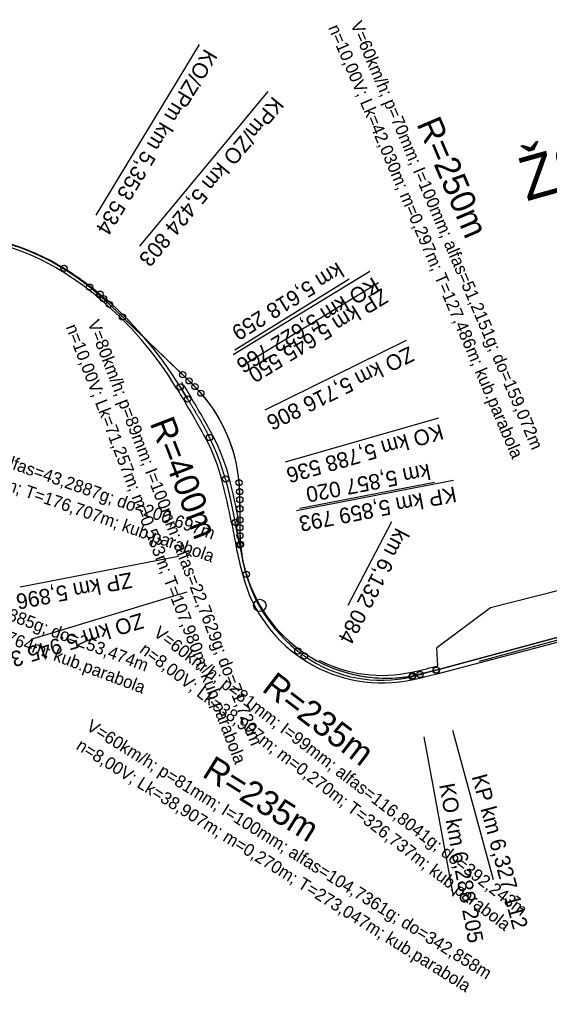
# Model space of a CAD drawing. Extents: x -504999 to -493096, y -1330712 to -1305226.
# Drawn here: x -502934 to -502082, y -1330075 to -1328510 of the extents above; entities that cross this region are included whole.
import ezdxf

# ---------------------------------------------------------------- set-up
doc = ezdxf.new("R2010")
doc.units = 0
for name, color, linetype in [('0_HM', 7, 'Continuous'), ('0_NAVRH V_60_povodnej osi', 7, 'Continuous'), ('0_NAVRH V_80KMH', 7, 'Continuous'), ('0_obluky', 7, 'Continuous'), ('0_STANICE', 7, 'Continuous'), ('0_stanicenie oblukov', 7, 'Continuous'), ('0_SUčASNA KOLAJ', 7, 'Continuous'), ('Level 1', 7, 'Continuous'), ('PHS', 7, 'Continuous')]:
    doc.layers.add(name, color=color, linetype=linetype)

msp = doc.modelspace()

# ---------------------------------------------------------------- linework, layer by layer
at = {"layer": '0_HM'}
msp.add_circle((-502547.5, -1329452.5), 10, dxfattribs=at)
at = {"layer": '0_NAVRH V_60_povodnej osi'}
for p, q in [((-502769, -1328987.9), (-502671.7, -1329081.4)), ((-502579.7, -1329297.2), (-502579.7, -1329317.3))]:
    msp.add_line(p, q, dxfattribs=at)
for points in [[(-502768.3, -1328988.6), (-502769, -1328987.9), (-502769.7, -1328987.2), (-502770.4, -1328986.6), (-502771.1, -1328985.9), (-502771.9, -1328985.2), (-502772.6, -1328984.5), (-502773.3, -1328983.8), (-502774, -1328983.1), (-502774.8, -1328982.4), (-502775.5, -1328981.7), (-502776.2, -1328981), (-502776.9, -1328980.3), (-502777.7, -1328979.6), (-502778.4, -1328978.9), (-502779.1, -1328978.2), (-502779.8, -1328977.5), (-502780.6, -1328976.8), (-502781.3, -1328976.2), (-502782, -1328975.5), (-502782.7, -1328974.8), (-502783.5, -1328974.1), (-502784.2, -1328973.4), (-502784.9, -1328972.7), (-502785.7, -1328972), (-502786.4, -1328971.3), (-502787.1, -1328970.6), (-502787.9, -1328970), (-502788.6, -1328969.3), (-502789.3, -1328968.6), (-502790.1, -1328967.9), (-502790.8, -1328967.2), (-502791.5, -1328966.5), (-502792.3, -1328965.9), (-502793, -1328965.2), (-502793.7, -1328964.5), (-502794.5, -1328963.8), (-502795.2, -1328963.1), (-502796, -1328962.5), (-502796.7, -1328961.8), (-502797.4, -1328961.1), (-502798.2, -1328960.4), (-502798.9, -1328959.8), (-502799.7, -1328959.1), (-502800.4, -1328958.4), (-502801.2, -1328957.8), (-502801.9, -1328957.1), (-502802.7, -1328956.4), (-502803.4, -1328955.8), (-502804.2, -1328955.1), (-502804.9, -1328954.4), (-502805.7, -1328953.8), (-502806.4, -1328953.1), (-502807.2, -1328952.4), (-502807.9, -1328951.8), (-502808.7, -1328951.1), (-502809.5, -1328950.5), (-502810.2, -1328949.8), (-502811, -1328949.2), (-502811.8, -1328948.5), (-502812.5, -1328947.9), (-502813.3, -1328947.2), (-502814.1, -1328946.6), (-502814.8, -1328945.9), (-502815.6, -1328945.3), (-502816.4, -1328944.6), (-502817.2, -1328944), (-502817.9, -1328943.4), (-502818.7, -1328942.7), (-502819.5, -1328942.1), (-502820.3, -1328941.5), (-502821.1, -1328940.8)], [(-502671.7, -1329081.4), (-502671, -1329082.1), (-502670.3, -1329082.8), (-502669.6, -1329083.5), (-502668.9, -1329084.2), (-502668.1, -1329084.9), (-502667.4, -1329085.6), (-502666.7, -1329086.2), (-502666, -1329086.9), (-502665.3, -1329087.6), (-502664.5, -1329088.3), (-502663.8, -1329089), (-502663.1, -1329089.7), (-502662.4, -1329090.4), (-502661.7, -1329091.1), (-502661, -1329091.8), (-502660.2, -1329092.5), (-502659.5, -1329093.2), (-502658.8, -1329093.9), (-502658.1, -1329094.6), (-502657.4, -1329095.3), (-502656.7, -1329096.1), (-502656, -1329096.8), (-502655.3, -1329097.5), (-502654.6, -1329098.2), (-502653.9, -1329098.9), (-502653.2, -1329099.6), (-502652.5, -1329100.3), (-502651.8, -1329101), (-502651.1, -1329101.8), (-502650.4, -1329102.5), (-502649.7, -1329103.2), (-502649, -1329103.9), (-502648.3, -1329104.7), (-502647.7, -1329105.4), (-502647, -1329106.1), (-502646.3, -1329106.9), (-502645.6, -1329107.6), (-502644.9, -1329108.4), (-502644.3, -1329109.1), (-502643.6, -1329109.8), (-502642.9, -1329110.6), (-502642.3, -1329111.3)], [(-502579.7, -1329297.2), (-502579.7, -1329296.2), (-502579.7, -1329295.2), (-502579.7, -1329294.2), (-502579.7, -1329293.2), (-502579.7, -1329292.2), (-502579.7, -1329291.2), (-502579.7, -1329290.2), (-502579.7, -1329289.2), (-502579.7, -1329288.2), (-502579.7, -1329287.2), (-502579.8, -1329286.2), (-502579.8, -1329285.2), (-502579.8, -1329284.2), (-502579.8, -1329283.2), (-502579.8, -1329282.2), (-502579.8, -1329281.2), (-502579.8, -1329280.2), (-502579.8, -1329279.2), (-502579.8, -1329278.2), (-502579.9, -1329277.2), (-502579.9, -1329276.2), (-502579.9, -1329275.2), (-502579.9, -1329274.2), (-502580, -1329273.2), (-502580, -1329272.2), (-502580, -1329271.2), (-502580.1, -1329270.2), (-502580.1, -1329269.2), (-502580.1, -1329268.2), (-502580.2, -1329267.2), (-502580.2, -1329266.2), (-502580.3, -1329265.2), (-502580.3, -1329264.2), (-502580.4, -1329263.2), (-502580.4, -1329262.2), (-502580.5, -1329261.2), (-502580.6, -1329260.2), (-502580.6, -1329259.2), (-502580.7, -1329258.2), (-502580.8, -1329257.2), (-502580.9, -1329256.2), (-502580.9, -1329255.2)], [(-502579.7, -1329315.2), (-502579.7, -1329316.2), (-502579.7, -1329317.3), (-502579.7, -1329318.3), (-502579.7, -1329319.3), (-502579.7, -1329320.3), (-502579.7, -1329321.3), (-502579.7, -1329322.4), (-502579.7, -1329323.4), (-502579.7, -1329324.4), (-502579.7, -1329325.4), (-502579.7, -1329326.5), (-502579.7, -1329327.5), (-502579.7, -1329328.5), (-502579.6, -1329329.5), (-502579.6, -1329330.6), (-502579.6, -1329331.6), (-502579.6, -1329332.6), (-502579.6, -1329333.6), (-502579.6, -1329334.6), (-502579.5, -1329335.7), (-502579.5, -1329336.7), (-502579.5, -1329337.7), (-502579.5, -1329338.7), (-502579.4, -1329339.8), (-502579.4, -1329340.8), (-502579.3, -1329341.8), (-502579.3, -1329342.8), (-502579.3, -1329343.9), (-502579.2, -1329344.9), (-502579.2, -1329345.9), (-502579.1, -1329346.9), (-502579, -1329347.9), (-502579, -1329349), (-502578.9, -1329350), (-502578.8, -1329351), (-502578.8, -1329352), (-502578.7, -1329353.1), (-502578.6, -1329354.1)]]:
    msp.add_lwpolyline(points, dxfattribs=at)
for centre in [(-502821.1, -1328940.8), (-502768.3, -1328988.6), (-502671.7, -1329081.4), (-502642.3, -1329111.3), (-502580.9, -1329255.2), (-502579.7, -1329297.2), (-502579.7, -1329315.2), (-502578.6, -1329354.1), (-502301.9, -1329565.6), (-502264.1, -1329556.5)]:
    msp.add_circle(centre, 5, dxfattribs=at)
for centre, radius, start, end in [((-503071.5, -1329252.8), 400, 51.2431, 87.5506), ((-502830, -1329276.4), 250, 4.8619, 41.3185), ((-502344.4, -1329334.5), 235, 184.7885, 280.422)]:
    msp.add_arc(centre, radius, start, end, dxfattribs=at)
at = {"layer": '0_NAVRH V_80KMH'}
msp.add_lwpolyline([(-502264.1, -1329556.5), (-502265.1, -1329556.7), (-502266.1, -1329557), (-502267.1, -1329557.3), (-502268.1, -1329557.5), (-502269, -1329557.8), (-502270, -1329558.1), (-502271, -1329558.3), (-502272, -1329558.6), (-502273, -1329558.9), (-502274, -1329559.1), (-502275, -1329559.4), (-502276, -1329559.6), (-502277, -1329559.9), (-502277.9, -1329560.2), (-502278.9, -1329560.4), (-502279.9, -1329560.7), (-502280.9, -1329560.9), (-502281.9, -1329561.2), (-502282.9, -1329561.4), (-502283.9, -1329561.7), (-502284.9, -1329561.9), (-502285.9, -1329562.1), (-502286.9, -1329562.4), (-502287.9, -1329562.6), (-502288.9, -1329562.9), (-502289.9, -1329563.1), (-502290.9, -1329563.3), (-502291.9, -1329563.5), (-502292.9, -1329563.8), (-502293.9, -1329564), (-502294.9, -1329564.2), (-502295.9, -1329564.4), (-502296.9, -1329564.6), (-502297.9, -1329564.8), (-502298.9, -1329565), (-502299.9, -1329565.2), (-502300.9, -1329565.4), (-502301.9, -1329565.6)], dxfattribs=at)
at = {"layer": '0_obluky'}
for p, q in [((-502663.7, -1329120.6), (-502675.6, -1329101.2)), ((-502675.6, -1329101.2), (-502663.7, -1329120.6)), ((-502580, -1329355.1), (-502587, -1329318.8)), ((-502587, -1329318.8), (-502580, -1329355.1)), ((-502264, -1329556.4), (-501516.9, -1329353.9))]:
    msp.add_line(p, q, dxfattribs=at)
for points in [[(-502804.4, -1328952.1), (-502805.2, -1328951.4), (-502806, -1328950.8), (-502806.8, -1328950.2), (-502807.5, -1328949.5), (-502808.3, -1328948.9), (-502809.1, -1328948.3), (-502809.9, -1328947.6), (-502810.7, -1328947), (-502811.4, -1328946.4), (-502812.2, -1328945.7), (-502813, -1328945.1), (-502813.8, -1328944.5), (-502814.6, -1328943.9), (-502815.4, -1328943.2), (-502816.2, -1328942.6), (-502816.9, -1328942), (-502817.7, -1328941.4), (-502818.5, -1328940.8), (-502819.3, -1328940.2), (-502820.1, -1328939.5), (-502820.9, -1328938.9), (-502821.7, -1328938.3), (-502822.5, -1328937.7), (-502823.3, -1328937.1), (-502824.1, -1328936.5), (-502824.9, -1328935.9), (-502825.7, -1328935.3), (-502826.5, -1328934.7), (-502827.3, -1328934.1), (-502828.1, -1328933.5), (-502828.9, -1328932.9), (-502829.7, -1328932.3), (-502830.5, -1328931.7), (-502831.3, -1328931.1), (-502832.2, -1328930.5), (-502833, -1328929.9), (-502833.8, -1328929.4), (-502834.6, -1328928.8), (-502835.4, -1328928.2), (-502836.2, -1328927.6), (-502837.1, -1328927), (-502837.9, -1328926.4), (-502838.7, -1328925.9), (-502839.5, -1328925.3), (-502840.3, -1328924.7), (-502841.2, -1328924.2), (-502842, -1328923.6), (-502842.8, -1328923), (-502843.6, -1328922.5), (-502844.5, -1328921.9), (-502845.3, -1328921.3), (-502846.1, -1328920.8), (-502847, -1328920.2), (-502847.8, -1328919.7), (-502848.7, -1328919.1), (-502849.5, -1328918.6), (-502850.3, -1328918), (-502851.2, -1328917.5), (-502852, -1328916.9), (-502852.9, -1328916.4), (-502853.7, -1328915.8), (-502854.6, -1328915.3), (-502855.4, -1328914.7), (-502856.3, -1328914.2), (-502857.1, -1328913.7), (-502858, -1328913.1), (-502858.8, -1328912.6), (-502859.7, -1328912.1), (-502860.5, -1328911.6), (-502861.4, -1328911), (-502862.2, -1328910.5)], [(-502663.7, -1329120.6), (-502663.2, -1329121.5), (-502662.7, -1329122.3), (-502662.1, -1329123.2), (-502661.6, -1329124), (-502661.1, -1329124.9), (-502660.6, -1329125.8), (-502660, -1329126.6), (-502659.5, -1329127.5), (-502659, -1329128.3), (-502658.5, -1329129.2), (-502658, -1329130), (-502657.4, -1329130.9), (-502656.9, -1329131.8), (-502656.4, -1329132.6), (-502655.9, -1329133.5), (-502655.4, -1329134.3), (-502654.8, -1329135.2), (-502654.3, -1329136), (-502653.8, -1329136.9), (-502653.3, -1329137.8), (-502652.8, -1329138.6), (-502652.3, -1329139.5), (-502651.7, -1329140.3), (-502651.2, -1329141.2), (-502650.7, -1329142.1), (-502650.2, -1329142.9), (-502649.7, -1329143.8), (-502649.2, -1329144.7), (-502648.7, -1329145.5), (-502648.2, -1329146.4), (-502647.7, -1329147.2), (-502647.2, -1329148.1), (-502646.6, -1329149), (-502646.1, -1329149.8), (-502645.6, -1329150.7), (-502645.1, -1329151.6), (-502644.6, -1329152.4), (-502644.1, -1329153.3), (-502643.6, -1329154.2), (-502643.1, -1329155.1), (-502642.6, -1329155.9), (-502642.1, -1329156.8), (-502641.6, -1329157.7), (-502641.1, -1329158.5), (-502640.7, -1329159.4), (-502640.2, -1329160.3), (-502639.7, -1329161.2), (-502639.2, -1329162.1), (-502638.7, -1329162.9), (-502638.2, -1329163.8), (-502637.7, -1329164.7), (-502637.2, -1329165.6), (-502636.8, -1329166.4), (-502636.3, -1329167.3), (-502635.8, -1329168.2), (-502635.3, -1329169.1), (-502634.9, -1329170), (-502634.4, -1329170.9), (-502633.9, -1329171.8), (-502633.5, -1329172.6), (-502633, -1329173.5), (-502632.5, -1329174.4), (-502632.1, -1329175.3), (-502631.6, -1329176.2), (-502631.1, -1329177.1), (-502630.7, -1329178), (-502630.2, -1329178.9), (-502629.8, -1329179.8), (-502629.3, -1329180.7), (-502628.9, -1329181.6), (-502628.4, -1329182.5)], [(-502587, -1329318.8), (-502587.2, -1329317.8), (-502587.4, -1329316.9), (-502587.6, -1329315.9), (-502587.8, -1329314.9), (-502588, -1329313.9), (-502588.2, -1329312.9), (-502588.4, -1329311.9), (-502588.5, -1329310.9), (-502588.7, -1329310), (-502588.9, -1329309), (-502589.1, -1329308), (-502589.3, -1329307), (-502589.5, -1329306), (-502589.7, -1329305), (-502589.9, -1329304.1), (-502590.1, -1329303.1), (-502590.3, -1329302.1), (-502590.5, -1329301.1), (-502590.7, -1329300.1), (-502590.9, -1329299.1), (-502591.1, -1329298.2), (-502591.3, -1329297.2), (-502591.5, -1329296.2), (-502591.7, -1329295.2), (-502591.9, -1329294.2), (-502592.1, -1329293.2), (-502592.3, -1329292.3), (-502592.5, -1329291.3), (-502592.7, -1329290.3), (-502592.9, -1329289.3), (-502593.1, -1329288.3), (-502593.3, -1329287.4), (-502593.5, -1329286.4), (-502593.7, -1329285.4), (-502593.9, -1329284.4), (-502594.1, -1329283.4), (-502594.3, -1329282.4), (-502594.6, -1329281.5), (-502594.8, -1329280.5), (-502595, -1329279.5), (-502595.2, -1329278.5), (-502595.4, -1329277.5), (-502595.6, -1329276.6), (-502595.9, -1329275.6), (-502596.1, -1329274.6), (-502596.3, -1329273.6), (-502596.5, -1329272.7), (-502596.8, -1329271.7), (-502597, -1329270.7), (-502597.2, -1329269.7), (-502597.5, -1329268.8), (-502597.7, -1329267.8), (-502597.9, -1329266.8), (-502598.2, -1329265.8), (-502598.4, -1329264.9), (-502598.7, -1329263.9), (-502598.9, -1329262.9), (-502599.2, -1329261.9), (-502599.4, -1329261), (-502599.7, -1329260), (-502599.9, -1329259), (-502600.2, -1329258), (-502600.4, -1329257.1), (-502600.7, -1329256.1), (-502601, -1329255.1), (-502601.2, -1329254.2), (-502601.5, -1329253.2), (-502601.8, -1329252.2), (-502602, -1329251.2), (-502602.3, -1329250.3), (-502602.6, -1329249.3)], [(-502580, -1329355.1), (-502579.8, -1329356.1), (-502579.7, -1329357.1), (-502579.5, -1329358.1), (-502579.3, -1329359.1), (-502579.1, -1329360.1), (-502578.9, -1329361.1), (-502578.7, -1329362.1), (-502578.5, -1329363.1), (-502578.3, -1329364.1), (-502578.1, -1329365.1), (-502577.9, -1329366), (-502577.7, -1329367), (-502577.5, -1329368), (-502577.3, -1329369), (-502577.1, -1329370), (-502576.9, -1329371), (-502576.7, -1329372), (-502576.5, -1329373), (-502576.3, -1329374), (-502576.1, -1329375), (-502575.9, -1329376), (-502575.7, -1329377), (-502575.5, -1329377.9), (-502575.2, -1329378.9), (-502575, -1329379.9), (-502574.8, -1329380.9), (-502574.6, -1329381.9), (-502574.3, -1329382.9), (-502574.1, -1329383.9), (-502573.9, -1329384.9), (-502573.7, -1329385.8), (-502573.4, -1329386.8), (-502573.2, -1329387.8), (-502572.9, -1329388.8), (-502572.7, -1329389.8), (-502572.4, -1329390.8), (-502572.2, -1329391.7), (-502571.9, -1329392.7), (-502571.7, -1329393.7), (-502571.4, -1329394.7), (-502571.2, -1329395.7), (-502570.9, -1329396.6), (-502570.6, -1329397.6), (-502570.3, -1329398.6), (-502570.1, -1329399.6), (-502569.8, -1329400.5), (-502569.5, -1329401.5), (-502569.2, -1329402.5)], [(-502264, -1329556.4), (-502264.9, -1329556.7), (-502265.9, -1329557), (-502266.9, -1329557.2), (-502267.9, -1329557.5), (-502268.9, -1329557.8), (-502269.9, -1329558), (-502270.9, -1329558.3), (-502271.9, -1329558.6), (-502272.8, -1329558.8), (-502273.8, -1329559.1), (-502274.8, -1329559.3), (-502275.8, -1329559.6), (-502276.8, -1329559.9), (-502277.8, -1329560.1), (-502278.8, -1329560.4), (-502279.8, -1329560.6), (-502280.8, -1329560.9), (-502281.8, -1329561.1), (-502282.8, -1329561.4), (-502283.7, -1329561.6), (-502284.7, -1329561.9), (-502285.7, -1329562.1), (-502286.7, -1329562.3), (-502287.7, -1329562.6), (-502288.7, -1329562.8), (-502289.7, -1329563), (-502290.7, -1329563.3), (-502291.7, -1329563.5), (-502292.7, -1329563.7), (-502293.7, -1329563.9), (-502294.7, -1329564.2), (-502295.7, -1329564.4), (-502296.7, -1329564.6), (-502297.7, -1329564.8), (-502298.7, -1329565), (-502299.7, -1329565.2), (-502300.8, -1329565.4), (-502301.8, -1329565.6)]]:
    msp.add_lwpolyline(points, dxfattribs=at)
for centre in [(-502862.2, -1328910.5), (-502804.4, -1328952.1), (-502804.4, -1328952.1), (-502675.6, -1329101.2), (-502663.7, -1329120.6), (-502628.4, -1329182.5), (-502602.6, -1329249.3), (-502587, -1329318.8), (-502580, -1329355.1), (-502569.2, -1329402.5), (-502301.8, -1329565.6), (-502264, -1329556.4)]:
    msp.add_circle(centre, 5, dxfattribs=at)
for centre, radius, start, end in [((-503069.4, -1329252.7), 400, 58.803, 87.5506), ((-503187.7, -1329413.7), 600, 31.3913, 50.2953), ((-502987.1, -1329359.6), 400, 16.0107, 26.2852), ((-502344.3, -1329334.4), 235, 196.8292, 280.422)]:
    msp.add_arc(centre, radius, start, end, dxfattribs=at)
at = {"layer": '0_stanicenie oblukov'}
for p, q in [((-502810.4, -1328825), (-502644.4, -1328550.8)), ((-502740.6, -1328875.2), (-502533.9, -1328626.3)), ((-502590.2, -1329049.1), (-502370.8, -1328915.2)), ((-502578.3, -1329068.5), (-502356.6, -1328933.2)), ((-502538.8, -1329138.2), (-502311.9, -1329026.2)), ((-502506.5, -1329221.7), (-502259.7, -1329150.9)), ((-502488.8, -1329299.9), (-502236.2, -1329251.2)), ((-502678.2, -1329374), (-502932.7, -1329423.1)), ((-502664.9, -1329431.4), (-502915.6, -1329507.2)), ((-501950.7, -1329471.5), (-502264.1, -1329556.5)), ((-502237.8, -1329652.9), (-502172.7, -1329893.2)), ((-502283.7, -1329663.9), (-502237.2, -1329916.7))]:
    msp.add_line(p, q, dxfattribs=at)
at = {"layer": '0_SUčASNA KOLAJ'}
for p, q in [((-502664.8, -1329088.1), (-502764.4, -1328992.3)), ((-502579.7, -1329286.3), (-502579.7, -1329327.4))]:
    msp.add_line(p, q, dxfattribs=at)
for points in [[(-502789.4, -1328968.3), (-502790.1, -1328967.6), (-502790.8, -1328966.9), (-502791.6, -1328966.2), (-502792.3, -1328965.5), (-502793, -1328964.9), (-502793.7, -1328964.2), (-502794.4, -1328963.5), (-502795.2, -1328962.8), (-502795.9, -1328962.1), (-502796.6, -1328961.4), (-502797.4, -1328960.7), (-502798.1, -1328960), (-502798.8, -1328959.4)], [(-502661.2, -1329091.5), (-502660.5, -1329092.2), (-502659.8, -1329092.9), (-502659, -1329093.6), (-502658.3, -1329094.3), (-502657.6, -1329095), (-502656.9, -1329095.7), (-502656.2, -1329096.4), (-502655.5, -1329097.1), (-502654.7, -1329097.8), (-502654, -1329098.5), (-502653.3, -1329099.2), (-502652.6, -1329099.9), (-502651.9, -1329100.6)], [(-502579.7, -1329282.6), (-502579.7, -1329281.6), (-502579.7, -1329280.6), (-502579.7, -1329279.6), (-502579.7, -1329278.6), (-502579.7, -1329277.6), (-502579.8, -1329276.6), (-502579.8, -1329275.6), (-502579.8, -1329274.6), (-502579.8, -1329273.6), (-502579.8, -1329272.6), (-502579.8, -1329271.6), (-502579.8, -1329270.6), (-502579.9, -1329269.6)], [(-502579.7, -1329327.3), (-502579.7, -1329328.3), (-502579.7, -1329329.3), (-502579.7, -1329330.3), (-502579.7, -1329331.3), (-502579.7, -1329332.3), (-502579.7, -1329333.3), (-502579.7, -1329334.3), (-502579.7, -1329335.3), (-502579.7, -1329336.3), (-502579.6, -1329337.3), (-502579.6, -1329338.3), (-502579.6, -1329339.3), (-502579.6, -1329340.3)], [(-502486.5, -1329525.9), (-502485.8, -1329526.5), (-502485, -1329527.1), (-502484.2, -1329527.7), (-502483.4, -1329528.3), (-502482.6, -1329528.9), (-502481.8, -1329529.5), (-502481, -1329530.1), (-502480.2, -1329530.7), (-502479.4, -1329531.3), (-502478.6, -1329531.9), (-502477.8, -1329532.5), (-502476.9, -1329533.1), (-502476.1, -1329533.7)], [(-502290.1, -1329563.5), (-502291.1, -1329563.8), (-502292, -1329564), (-502293, -1329564.3), (-502294, -1329564.5), (-502294.9, -1329564.8), (-502295.9, -1329565.1), (-502296.9, -1329565.3), (-502297.8, -1329565.6), (-502298.8, -1329565.8), (-502299.8, -1329566.1), (-502300.7, -1329566.3), (-502301.7, -1329566.5), (-502302.7, -1329566.8)]]:
    msp.add_lwpolyline(points, dxfattribs=at)
for centre, radius in [((-502798.8, -1328959.4), 5), ((-502789.4, -1328968.3), 5), ((-502661.2, -1329091.5), 5), ((-502651.9, -1329100.6), 5), ((-502579.9, -1329269.6), 5), ((-502579.7, -1329282.6), 5), ((-502579.7, -1329327.3), 5), ((-502579.6, -1329340.3), 5), ((-502486.5, -1329525.9), 5), ((-502486.5, -1329525.9), 5), ((-502476.1, -1329533.7), 5), ((-502302.7, -1329566.8), 5), ((-502290.1, -1329563.5), 5), ((-502289.1, -1329563.2), 1)]:
    msp.add_circle(centre, radius, dxfattribs=at)
for centre, radius, start, end in [((-503071.3, -1329252.2), 400, 47.0681, 91.7257), ((-502829.8, -1329276.3), 250, 1.5331, 44.6473), ((-502334.7, -1329333.6), 245, 181.5637, 231.6921), ((-502352.6, -1329357.7), 215, 234.9449, 283.4347)]:
    msp.add_arc(centre, radius, start, end, dxfattribs=at)
at = {"layer": 'Level 1'}
msp.add_lwpolyline([(-500417.5, -1329061.1), (-500981.3, -1329214.1), (-501250.5, -1329287.1), (-501600.6, -1329382.1), (-502121.9, -1329522.8), (-502195.1, -1329542.5)], dxfattribs=at)
at = {"layer": 'PHS'}
for p, q in [((-502587.8, -1329041.4), (-502403.9, -1328927.3)), ((-502483.5, -1329296), (-502266.9, -1329254.3)), ((-502405.8, -1329451.8), (-502335.4, -1329317.4)), ((-502262.4, -1329562.2), (-502063.3, -1329509.9)), ((-502261.5, -1329549.5), (-502263.1, -1329520.5)), ((-502265.5, -1329550.6), (-502261.5, -1329549.5))]:
    msp.add_line(p, q, dxfattribs=at)
msp.add_lwpolyline([(-501360, -1329303), (-501434.7, -1329321.4), (-501760.6, -1329350.8), (-502176.6, -1329456.3), (-502263.1, -1329520.5)], dxfattribs=at)
for centre, radius, start, end in [((-503063, -1329231.3), 372.4, 57.9626, 88.391), ((-503155, -1329378.3), 545.9, 50.5648, 57.9626), ((-503175.1, -1329402.8), 577.5, 31.1219, 50.5648), ((-503175.1, -1329402.8), 589.5, 31.1219, 31.567), ((-500600.9, -1327848.5), 2429.5, 211.1219, 211.6606), ((-500600.9, -1327848.5), 2417.5, 211.1219, 211.6606), ((-503543.2, -1329663), 1027.2, 27.7098, 31.6606), ((-503543.2, -1329663), 1039.2, 27.7098, 31.6606), ((-502905.9, -1329328.2), 307.4, 14.586, 27.7098), ((-502905.9, -1329328.2), 319.4, 14.586, 27.7098), ((-503602.5, -1329509.5), 1027.2, 10.6353, 14.586), ((-503602.5, -1329509.5), 1039.2, 10.7898, 14.586), ((-498723.8, -1328593.4), 3936.7, 190.6353, 191.174), ((-501779.4, -1329197), 822.2, 191.174, 194.5847), ((-502351.2, -1329345.7), 231.3, 194.5847, 282.6666), ((-502351.2, -1329345.7), 219.3, 242.5828, 282.6666), ((-502568.6, -1328378.2), 1211, 282.6666, 284.4962), ((-502568.6, -1328378.2), 1223, 282.6666, 284.4995)]:
    msp.add_arc(centre, radius, start, end, dxfattribs=at)

# ---------------------------------------------------------------- texts
at = {"layer": '0_NAVRH V_60_povodnej osi'}
for s, height, rotation, p in [('V=60km/h; p=70mm; I=100mm; alfas=51,2151g; do=159,072m', 20, 293.0902, (-502402.3, -1328518.2)), ('n=10,00V; Lk=42,030m; m=0,297m; T=127,486m; kub.parabola', 20, 293.0902, (-502438, -1328523.6)), ('R=250m', 40, 293.0902, (-502296, -1328678.2)), ('V=80km/h; p=89mm; I=100mm; alfas=51,6885g; do=253,474m', 20, 339.3969, (-503429.1, -1329296.8)), ('n=10,00V; Lk=71,257m; m=0,533m; T=207,764m; kub.parabola', 20, 339.3969, (-503443.1, -1329328.9)), ('V=60km/h; p=81mm; I=99mm; alfas=116,8041g; do=392,243m', 20, 322.6053, (-502719.9, -1329500.1)), ('n=8,00V; Lk=38,907m; m=0,270m; T=326,737m; kub.parabola', 20, 322.6053, (-502742.4, -1329526.9)), ('R=235m', 40, 322.6053, (-502546, -1329589))]:
    msp.add_text(s, height=height, rotation=rotation, dxfattribs=at).set_placement(p)
at = {"layer": '0_obluky'}
for s, height, rotation, p in [('n=10,00V; Lk=71,257m; m=0,533m; T=107,980m; kub.parabola', 20, 291.1479, (-502859.8, -1329004.8)), ('V=80km/h; p=89mm; I=100mm; alfas=22,7629g; do=71,729m', 20, 291.1479, (-502824.8, -1328998.2)), ('V=80km/h; p=89mm; I=100mm; alfas=43,2887g; do=200,697m', 20, 340.5997, (-503327.1, -1329099.2)), ('n=10,00V; Lk=71,257m; m=0,533m; T=176,707m; kub.parabola', 20, 340.5997, (-503337.4, -1329132.7)), ('R=400m', 40, 291.1479, (-502724.9, -1329159.3)), ('V=60km/h; p=81mm; I=100mm; alfas=104,7361g; do=342,858m', 20, 328.0164, (-502828, -1329651.7)), ('n=8,00V; Lk=38,907m; m=0,270m; T=273,047m; kub.parabola', 20, 328.0164, (-502844.4, -1329682.7)), ('R=235m', 40, 328.0164, (-502642.1, -1329726.5))]:
    msp.add_text(s, height=height, rotation=rotation, dxfattribs=at).set_placement(p)
at = {"layer": '0_STANICE'}
msp.add_text('ŽST  KOMÁRNO', height=70, rotation=15.6199, dxfattribs=at).set_placement((-502118.8, -1328803))
at = {"layer": '0_stanicenie oblukov'}
for s, rotation, p in [('KO/ZPm km 5,353 534', 238.803, (-502635.9, -1328556)), ('KPm/ZO km 5,424 803', 230.2953, (-502526.2, -1328632.6)), ('KO km 5,622 766', 211.3913, (-502365.6, -1328923.7)), ('ZP km 5,645 550', 211.3913, (-502351.4, -1328941.8)), ('ZO km 5,716 806', 206.2852, (-502307.5, -1329035.2)), ('KO km 5,788 536', 196.0107, (-502256.9, -1329160.5)), ('KP km 5,859 793', 190.9046, (-502234.3, -1329261.1)), ('ZP km 5,896 748', 190.9046, (-502754.9, -1329399)), ('ZO km 5,945 348', 196.8292, (-502738.6, -1329464.2)), ('KP km 6,327 112', 285.1671, (-502207.2, -1329727.5)), ('KO km 6,288 205', 280.422, (-502259.4, -1329740.8))]:
    msp.add_text(s, height=25, rotation=rotation, dxfattribs=at).set_placement(p)
at = {"layer": 'PHS'}
for s, rotation, p in [('km 5,618 259', 211.8217, (-502423, -1328899.8)), ('km 5,857 020', 190.9124, (-502276.1, -1329224.3)), ('km 6,132 084', 242.3577, (-502328.6, -1329326.3))]:
    msp.add_text(s, height=25, rotation=rotation, dxfattribs=at).set_placement(p)

doc.saveas('drawing.dxf')
